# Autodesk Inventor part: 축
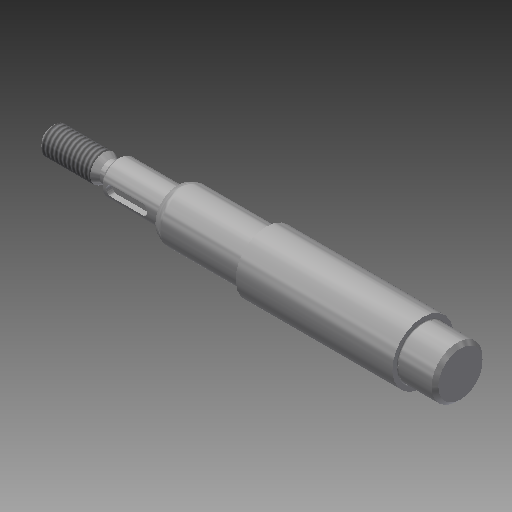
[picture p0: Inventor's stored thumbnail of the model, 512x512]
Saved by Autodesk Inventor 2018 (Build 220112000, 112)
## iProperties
Created: 2015-11
Part Number: 축
Material: 강철, 연강
Document SubType Name: Modeling
Designer: mduedu
Density: 1 g/cm^3
Appearance: 강철
Author: mduedu
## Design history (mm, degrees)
sketch "스케치1"
  geometry: L1 (-86, 0)-(86, 0); L2 (-86, 0)-(-86, 4); L3 (-86, 4)-(-70.732, 4); L4 (-70.732, 4)-(-69, 3); L5 (-69, 3)-(-67, 3); L6 (-67, 3)-(-67, 5); L7 (-67, 5)-(-49, 5); L8 (-49, 5)-(-49, 6.55); L9 (-47.355, 7.5)-(-23, 7.5); L10 (-23, 7.5)-(-23, 9); L11 (0, 0)-(0, 9); L12 (86, 4)-(70.732, 4); L13 (70.732, 4)-(69, 3); L14 (69, 3)-(67, 3); L15 (67, 3)-(67, 5); L16 (67, 5)-(49, 5); L17 (23, 7.5)-(23, 9); L18 (86, 0)-(86, 4); L19 (-23, 9)-(23, 9); L20 (-49, 6.55)-(-47.355, 7.5); L21 (47.355, 7.5)-(23, 7.5); L22 (49, 6.55)-(47.355, 7.5); L23 (49, 5)-(49, 6.55); 1 further point
  constraints: 46 end point, 10 symmetric about line, 6 perpendicular, 5 parallel, 2 midpoint, 1 coincident, 1 horizontal
  dimensions: "d0" = 172 distance of L1.start L1.end (derived); "d1" = 8 diameter of L3 L1; "d2" = 30 deg angle of L4 L5; "d3" = 6 diameter of L5 L1; "d4" = 10 diameter of L7 L1; "d5" = 15 diameter of L9 L1; "d6" = 18 diameter of L19 L1; "d8" = 18 distance of L6.end L7.end; "d9" = 46 distance of L10.end L17.end; "d10" = 2 distance of L4.end L5.end; "d11" = 17 distance from line of L4.end L2; "d16" = 13.1 diameter of L8.end L1; "d17" = 30 deg angle of L20 L9; "d18" = 26 distance between parallel lines of L10 L8
revolve "회전1" sketch "스케치1" stored, may be unused: angle "d12" = 90 deg
chamfer "모따기1" distance "d13" = 1; stored, may be unused: second distance "d14" = 2, angle "d15" = 45 deg
fillet "모깎기3" dims "d35" = 4
node "작업 평면1"
sketch "스케치2" dims "d23" = 12
  geometry: L1 (-5.5, 1.5)-(3.5, 1.5); L2 (3.5, 1.5)-(3.5, -1.5); L3 (3.5, -1.5)-(-5.5, -1.5); L4 (-5.5, -1.5)-(-5.5, 1.5); L5 (-9, -4)-(-9, 4) reference; 3 further points
  constraints: 8 end point, 2 midpoint, 2 parallel, 2 vertical alignment, 1 horizontal, 1 perpendicular, 4 other
  dimensions: "d21" = 3 distance between parallel lines of L3 L1; "d24" = 2 dimension on L5
extrude "돌출1" cut sketch "스케치2" distance "d25" = 1.8; taper "d26" = 0 deg
feature "스레드1" dims "d27" = 10, "d28" = 0
feature "스레드2" dims "d29" = 10, "d30" = 0
chamfer "모따기2" distance "d31" = 1; stored, may be unused: second distance "d32" = 2, angle "d33" = 45 deg
fillet "모깎기2" dims "d34" = 0.3
node "작업 평면2"
sketch "스케치3"
  geometry: C1 r 7.5 at (0, 0) reference; 1 further point
extrude "돌출2" cut sketch "스케치3" extent not by distance; stored distance "d37" = 10; taper "d38" = 0 deg
chamfer "모따기3" distance "d39" = 1; stored, may be unused: second distance "d40" = 2, angle "d41" = 45 deg
node "솔리드1"
mirror "대칭1"
node "절단 모서리 투영1"
other parameters: "d36" = 11
